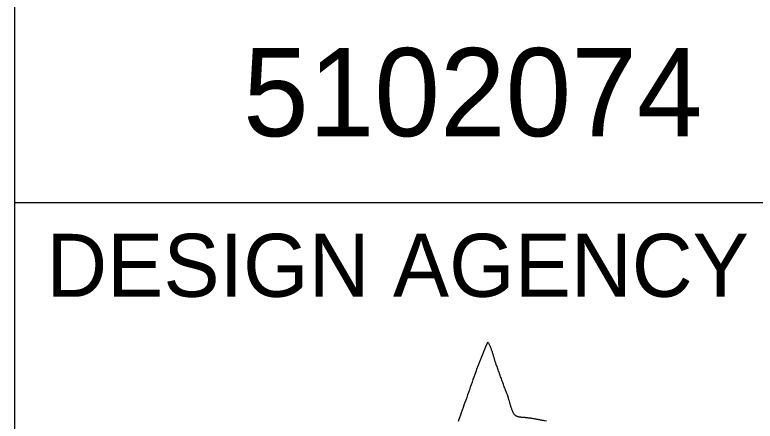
# Model space of a CAD drawing. Extents: x 0 to 34, y 0 to 22.
# Drawn here: x 32 to 33.175, y 4.652 to 5.298 of the extents above; entities that cross this region are included whole.
import ezdxf

# ---------------------------------------------------------------- set-up
doc = ezdxf.new("R2010")
doc.units = 0
for name, color, linetype in [('SH_Border', 7, 'Continuous'), ('SH_Data', 7, 'Continuous'), ('SH_Text', 7, 'Continuous')]:
    doc.layers.add(name, color=color, linetype=linetype)

msp = doc.modelspace()

# ---------------------------------------------------------------- linework, layer by layer
at = {"layer": 'SH_Border'}
for p, q in [((32, 0.5), (32, 21.5)), ((32, 5), (33.5, 5))]:
    msp.add_line(p, q, dxfattribs=at)
at = {"layer": 'SH_Text'}
for points in [[(32.7502, 4.7781), (32.7485, 4.7743), (32.7468, 4.7704), (32.7451, 4.7665), (32.7435, 4.7625), (32.742, 4.7585), (32.7404, 4.7546), (32.7388, 4.7506), (32.7372, 4.7466), (32.7357, 4.7426), (32.7342, 4.7386), (32.7326, 4.7346), (32.7312, 4.7306), (32.7297, 4.7265), (32.7283, 4.7225), (32.7268, 4.7185), (32.7254, 4.7144), (32.724, 4.7104), (32.7226, 4.7063), (32.7211, 4.7023), (32.7197, 4.6982), (32.7183, 4.6941), (32.7169, 4.6901), (32.7154, 4.686), (32.7141, 4.682), (32.7126, 4.678), (32.7112, 4.674), (32.7098, 4.6699), (32.7084, 4.6659), (32.7069, 4.6619), (32.7055, 4.6579), (32.704, 4.654)], [(32.7626, 4.7464), (32.7622, 4.7474), (32.7618, 4.7483), (32.7616, 4.7493), (32.7612, 4.7503), (32.761, 4.7514), (32.7606, 4.7524), (32.7603, 4.7535), (32.76, 4.7546), (32.7597, 4.7556), (32.7593, 4.7568), (32.7591, 4.7579), (32.7587, 4.759), (32.7583, 4.7601), (32.758, 4.7612), (32.7576, 4.7623), (32.7572, 4.7634), (32.7569, 4.7644), (32.7565, 4.7655), (32.7561, 4.7666), (32.7557, 4.7677), (32.7553, 4.7687), (32.7548, 4.7698), (32.7545, 4.7708), (32.754, 4.7718), (32.7535, 4.7728), (32.753, 4.7738), (32.7525, 4.7746), (32.7519, 4.7756), (32.7514, 4.7764), (32.7508, 4.7773), (32.7502, 4.7781)], [(32.7826, 4.6909), (32.782, 4.6927), (32.7814, 4.6945), (32.7806, 4.6962), (32.78, 4.698), (32.7793, 4.6998), (32.7787, 4.7016), (32.778, 4.7033), (32.7774, 4.7052), (32.7766, 4.707), (32.776, 4.7087), (32.7753, 4.7105), (32.7747, 4.7123), (32.774, 4.7141), (32.7734, 4.7158), (32.7728, 4.7176), (32.772, 4.7195), (32.7714, 4.7213), (32.7708, 4.723), (32.7701, 4.7248), (32.7695, 4.7266), (32.7689, 4.7284), (32.7682, 4.7301), (32.7675, 4.732), (32.7669, 4.7338), (32.7663, 4.7356), (32.7656, 4.7374), (32.765, 4.7391), (32.7644, 4.7409), (32.7638, 4.7427), (32.7632, 4.7446), (32.7626, 4.7464)], [(32.7948, 4.661), (32.7942, 4.6616), (32.7936, 4.6622), (32.793, 4.6628), (32.7924, 4.6636), (32.7919, 4.6643), (32.7913, 4.6652), (32.7908, 4.6661), (32.7903, 4.667), (32.7899, 4.6679), (32.7895, 4.669), (32.789, 4.67), (32.7886, 4.6711), (32.7883, 4.6722), (32.7878, 4.6733), (32.7874, 4.6744), (32.7871, 4.6756), (32.7868, 4.6767), (32.7865, 4.6779), (32.7861, 4.679), (32.7859, 4.6801), (32.7855, 4.6813), (32.7851, 4.6824), (32.7849, 4.6835), (32.7846, 4.6845), (32.7843, 4.6855), (32.784, 4.6865), (32.7838, 4.6875), (32.7834, 4.6884), (32.7832, 4.6893), (32.7829, 4.6901), (32.7826, 4.6909)], [(32.704, 4.654), (32.7037, 4.653), (32.7033, 4.6521)], [(32.8108, 4.658), (32.8103, 4.658), (32.8099, 4.6581), (32.8094, 4.6581), (32.8089, 4.6581), (32.8084, 4.6582), (32.8078, 4.6582), (32.8073, 4.6582), (32.8067, 4.6582), (32.8062, 4.6584), (32.8056, 4.6584), (32.805, 4.6584), (32.8045, 4.6584), (32.8039, 4.6585), (32.8033, 4.6585), (32.8028, 4.6586), (32.8022, 4.6586), (32.8016, 4.6587), (32.8011, 4.6587), (32.8005, 4.6588), (32.8, 4.659), (32.7994, 4.6591), (32.7989, 4.6592), (32.7985, 4.6593), (32.7979, 4.6595), (32.7974, 4.6597), (32.7969, 4.6598), (32.7965, 4.6601), (32.796, 4.6603), (32.7956, 4.6605), (32.7952, 4.6608), (32.7948, 4.661)], [(32.8405, 4.6529), (32.8396, 4.6531), (32.8387, 4.6533), (32.8377, 4.6535), (32.8368, 4.6538), (32.8358, 4.6539), (32.8348, 4.6541), (32.8339, 4.6542), (32.8329, 4.6545), (32.8319, 4.6546), (32.8311, 4.6548), (32.8301, 4.655), (32.8291, 4.6552), (32.8282, 4.6553), (32.8272, 4.6556), (32.8262, 4.6557), (32.8253, 4.6559), (32.8243, 4.6561), (32.8233, 4.6562), (32.8223, 4.6564), (32.8214, 4.6565), (32.8204, 4.6567), (32.8194, 4.6568), (32.8185, 4.657), (32.8175, 4.6571), (32.8165, 4.6573), (32.8156, 4.6574), (32.8147, 4.6575), (32.8137, 4.6576), (32.8128, 4.6578), (32.8118, 4.6579), (32.8108, 4.658)], [(32.8436, 4.6523), (32.8405, 4.6529)]]:
    msp.add_lwpolyline(points, dxfattribs=at)

# ---------------------------------------------------------------- texts
at = {"layer": 'SH_Data'}
for s, height, p in [('5102074', 0.14, (32.3621, 5.105)), ('DESIGN AGENCY', 0.1, (32.05, 4.85))]:
    msp.add_text(s, height=height, dxfattribs=at).set_placement(p)

doc.saveas('drawing.dxf')
